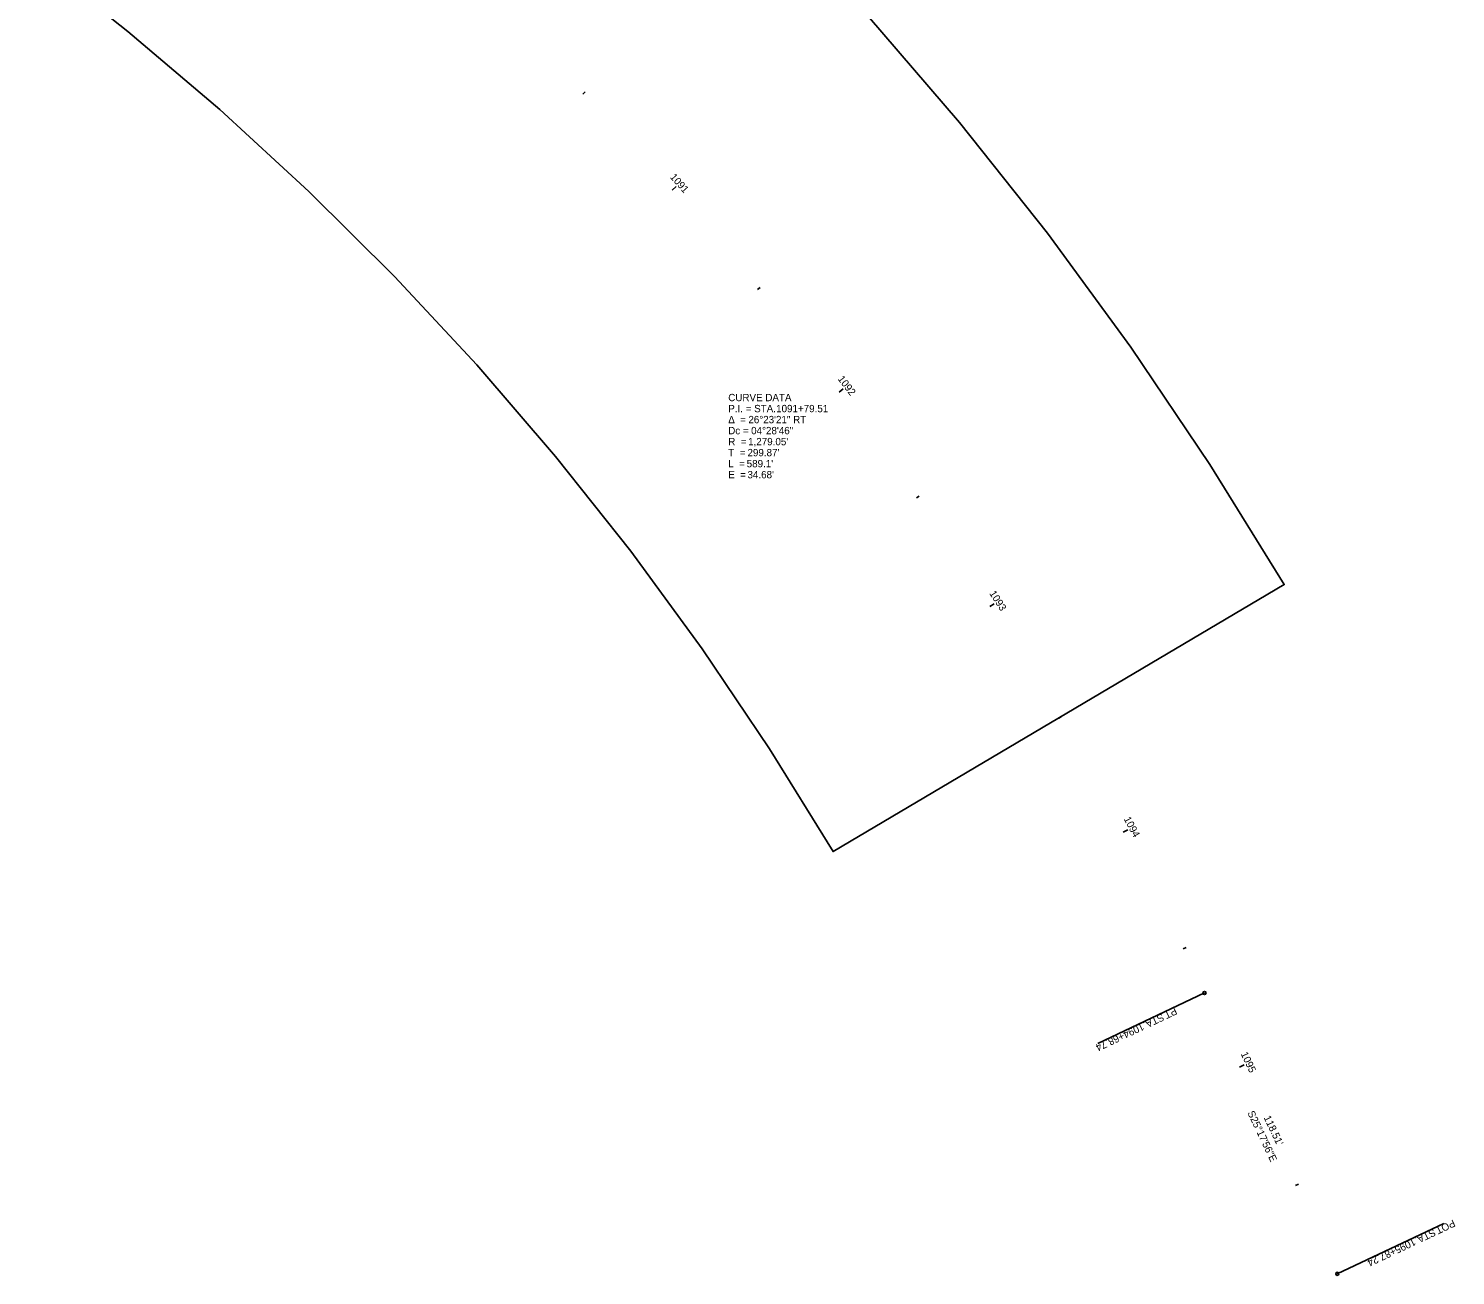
# Model space of a CAD drawing. Extents: x 1846275 to 1850613, y 577927 to 582526.
# Drawn here: x 1850069 to 1850613, y 577927 to 578403 of the extents above; entities that cross this region are included whole.
import ezdxf

# ---------------------------------------------------------------- set-up
doc = ezdxf.new("R2010")
doc.units = 0
for name, color, linetype in [('GE_P_Alignment_100_Cardinal_Points', 7, 'Continuous'), ('PM_P_Cells', 7, 'Continuous'), ('PM_P_Stop_Line', 7, 'Continuous'), ('PM_P_Transverse_Line', 7, 'Continuous'), ('SH_Named_Boundary', 7, 'Continuous'), ('XS_P_Pavt_Surface', 7, 'Continuous')]:
    doc.layers.add(name, color=color, linetype=linetype)

msp = doc.modelspace()

# ---------------------------------------------------------------- linework, layer by layer
at = {"layer": 'GE_P_Alignment_100_Cardinal_Points'}
for p, q in [((1850280.25, 578377.66), (1850281.12, 578378.49)), ((1850314.31, 578341.06), (1850315.8, 578342.39)), ((1850346.91, 578303.15), (1850347.84, 578303.91)), ((1850378.01, 578264), (1850379.6, 578265.21)), ((1850407.55, 578223.66), (1850408.53, 578224.35)), ((1850435.49, 578182.2), (1850437.17, 578183.29)), ((1850461.79, 578139.68), (1850462.82, 578140.29)), ((1850486.41, 578096.17), (1850488.17, 578097.12)), ((1850509.31, 578051.72), (1850510.38, 578052.25)), ((1850530.8, 578006.58), (1850532.61, 578007.43)), ((1850552.16, 577961.37), (1850553.25, 577961.88))]:
    msp.add_line(p, q, dxfattribs=at)
at = {"layer": 'PM_P_Cells'}
for p, q in [((1850517.44, 578034.84), (1850476.75, 578015.61)), ((1850568.08, 577927.7), (1850608.76, 577946.93))]:
    msp.add_line(p, q, dxfattribs=at)
for centre in [(1850517.44, 578034.84), (1850568.08, 577927.7)]:
    msp.add_circle(centre, 0.6, dxfattribs=at)
at = {"layer": 'SH_Named_Boundary'}
msp.add_lwpolyline([(1850192.75, 578588.68), (1850068.76, 578431.75), (1850106.65, 578401.62), (1850141.78, 578371.79), (1850175.71, 578340.6), (1850208.4, 578308.11), (1850239.8, 578274.37), (1850269.85, 578239.42), (1850298.51, 578203.33), (1850325.74, 578166.15), (1850351.5, 578127.93), (1850375.74, 578088.74), (1850547.86, 578190.59), (1850519.5, 578236.44), (1850489.38, 578281.14), (1850457.53, 578324.63), (1850424, 578366.85), (1850388.85, 578407.72), (1850352.13, 578447.18), (1850313.9, 578485.18), (1850274.21, 578521.66), (1850233.13, 578556.56)], close=True, dxfattribs=at)

# ---------------------------------------------------------------- texts
at = {"layer": 'GE_P_Alignment_100_Cardinal_Points'}
for s, rotation, p in [('1091', 311.8169, (1850313.33, 578345.9)), ('1092', 307.3373, (1850377.33, 578269.01)), ('1093', 302.8577, (1850435.21, 578187.25)), ('1094', 298.3782, (1850486.52, 578101.22)), ('1095', 295.299, (1850531.17, 578011.64))]:
    msp.add_text(s, height=2.8, rotation=rotation, dxfattribs=at).set_placement(p)
at = {"layer": 'PM_P_Cells'}
for s, p in [('PT', (1850506.11, 578029.44)), ('1094+68.74', (1850493.57, 578023.51)), (' STA. ', (1850502.12, 578027.55)), ('POT', (1850612.26, 577948.53)), ('1095+87.24', (1850597.2, 577941.42)), (' STA. ', (1850605.74, 577945.46))]:
    msp.add_text(s, height=2.8, rotation=205.299, dxfattribs=at).set_placement(p)
at = {"layer": 'PM_P_Stop_Line'}
msp.add_text('S25°17\'56"E', height=2.8, rotation=295.299, dxfattribs=at).set_placement((1850533.74, 577989.11))
at = {"layer": 'PM_P_Transverse_Line'}
for s, p in [('CURVE DATA', (1850335.72, 578260.55)), ('P.I. = STA. ', (1850335.72, 578256.35)), ('1091+79.51', (1850353.99, 578256.35)), ('Δ  = ', (1850335.72, 578252.15)), ('26°23\'21" RT', (1850343.4, 578252.15)), ('Dc = ', (1850335.72, 578247.95)), ('R  = ', (1850335.72, 578243.75)), ("1,279.05'", (1850343.3, 578243.75)), ('04°28\'46"', (1850344.46, 578247.95)), ('T  = ', (1850335.72, 578239.55)), ("299.87'", (1850343.06, 578239.55)), ('L  = ', (1850335.72, 578235.35)), ("589.1'", (1850342.76, 578235.35)), ('E  = ', (1850335.72, 578231.15)), ("34.68'", (1850343.06, 578231.15))]:
    msp.add_text(s, height=2.8, dxfattribs=at).set_placement(p)
at = {"layer": 'XS_P_Pavt_Surface'}
msp.add_text("118.51'", height=2.8, rotation=295.299, dxfattribs=at).set_placement((1850539.94, 577987.33))

doc.saveas('drawing.dxf')
